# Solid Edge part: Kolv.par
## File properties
Author: Türk
Template: Iso Part.par
Last saved by: Türk
Revision: 4
Application: Solid Edge
Accuracy: 0,990
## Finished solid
Body 1: solid body, 33 faces, 75 edges, 44 vertices.
  Faces by surface: plane 21, cylinder 8, cone 4
  Edges by curve: line 40, circle 23, ellipse 12
Bounding box of the edges (mm): 88.000 x 52.500 x 88.000, from (-44, 0, -44) to (44, 52.5, 44).
Cylindrical faces by radius (mm): R9 x2, R11 x2, R40 x3, R44 x1
Conical faces (half-angle, radius in mm at the cone's reference point): 45 deg R41 x1, 45 deg R43.5 x1, 45 deg R44 x2
Planar faces by outward normal: +x 2, +y 3, +z 4, -x 2, -y 2, -z 4, oblique 4
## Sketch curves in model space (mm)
arc centre (0, 7.5, 0) radius 40 from (-21, 7.5, 34.0441) through (-40, 7.5, 0) to (-21, 7.5, -34.0441)
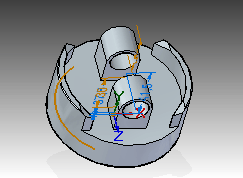
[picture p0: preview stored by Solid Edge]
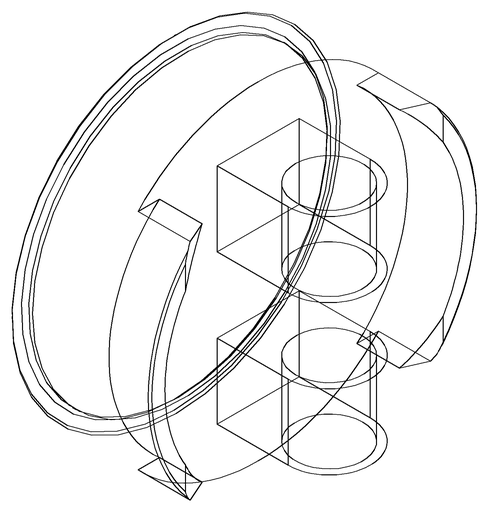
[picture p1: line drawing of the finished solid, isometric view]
